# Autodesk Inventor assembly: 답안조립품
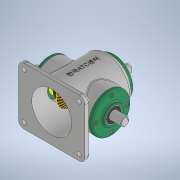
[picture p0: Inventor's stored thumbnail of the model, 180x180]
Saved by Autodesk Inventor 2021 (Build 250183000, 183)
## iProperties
Created: 2021-02
Part Number: 답안조립품
Document SubType Name: Assembly
Designer: 201-12
Author: 201-12
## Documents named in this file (16)
- C:\Users\201-12\Desktop\710215V1003\답안조립품.iam
- C:\Users\201-12\Desktop\710215V1003\본체.ipt
- C:\Users\201-12\Desktop\710215V1003\커버.ipt
- C:\Users\201-12\Desktop\710215V1003\서브 축.ipt
- 서브 축.ipt
- C:\Users\201-12\Desktop\710215V1003\키 4x4.ipt
- C:\Users\201-12\Desktop\710215V1003\서브 베벨기어.ipt
- C:\Users\201-12\Desktop\710215V1003\베어링 6203.ipt
- C:\Users\201-12\Desktop\710215V1003\메인 축.ipt
- 메인 축.ipt
- C:\Users\201-12\Desktop\710215V1003\키 5x5.ipt
- C:\Users\201-12\Desktop\710215V1003\메인 베벨기어.ipt
- C:\Users\201-12\Desktop\710215V1003\오일 실.ipt
- 오일 실.ipt
- C:\Users\201-12\Desktop\710215V1003\볼트 M4.ipt
- 볼트 M4.ipt
